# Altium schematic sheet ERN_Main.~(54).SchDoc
size A; SheetNumber: 1; SheetTotal: 3; SPICEModelCacheDBTNACQE: <root> / <DocumentId>DBTNACQE</DocumentId> / </root>
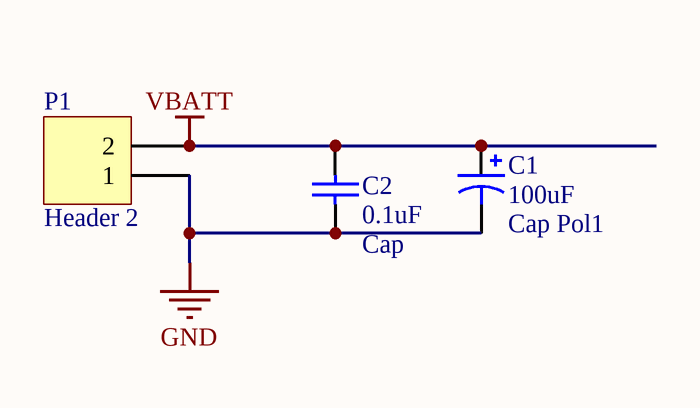
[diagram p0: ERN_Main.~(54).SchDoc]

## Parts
C1  Cap Pol1  value 100uF  [RB7.6-15]
C2  Cap  value 0.1uF  [RAD-0.3]
P1  Header 2  [HDR1X2]

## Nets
GND: C1.2 C2.1 P1.1
VBATT: C1.1 C2.2 P1.2

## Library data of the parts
C1 = Cap Pol1: Polarized Capacitor (Radial)
C2 = Cap: Capacitor
P1 = Header 2: Header, 2-Pin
